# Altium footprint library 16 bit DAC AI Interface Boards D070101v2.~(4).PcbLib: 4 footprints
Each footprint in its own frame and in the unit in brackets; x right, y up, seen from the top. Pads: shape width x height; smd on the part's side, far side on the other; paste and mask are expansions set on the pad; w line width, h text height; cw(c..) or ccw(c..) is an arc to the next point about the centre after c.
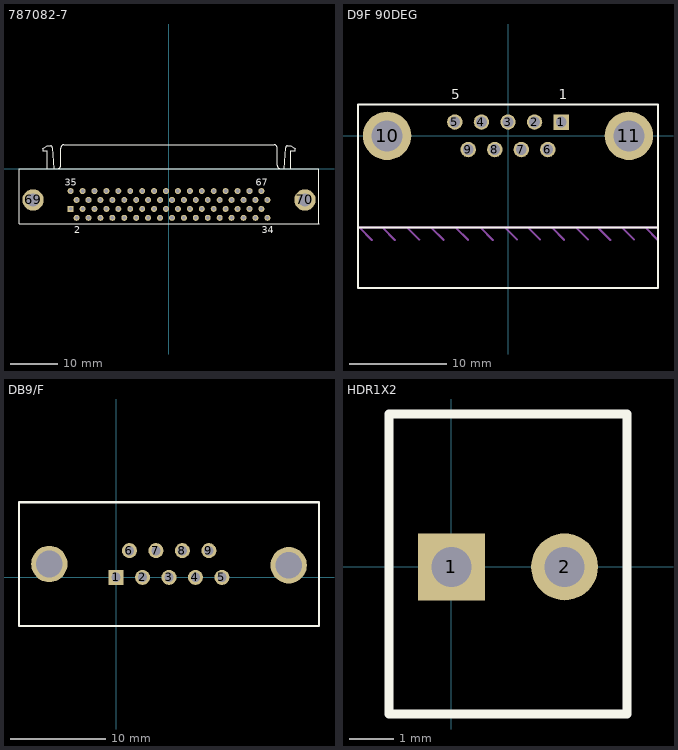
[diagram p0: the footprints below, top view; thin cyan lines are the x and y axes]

## 787082-7 [mm] "Connector; D Subminiature 050 Series; 68 Position; Right Angle"
height 10.44
pads (70):
  rect 1.27x1.27 hole 0.762: 1(-20.955,-8.555)
  round 1.27 hole 0.762: 2(-19.685,-10.46) 3(-18.415,-8.555) 4(-17.145,-10.46) 5(-15.875,-8.555) 6(-14.605,-10.46) 7(-13.335,-8.555) 8(-12.065,-10.46) 9(-10.795,-8.555) 10(-9.525,-10.46) 11(-8.255,-8.555) 12(-6.985,-10.46) 13(-5.715,-8.555) 14(-4.445,-10.46) 15(-3.175,-8.555) 16(-1.905,-10.46) 17(-0.635,-8.555) 18(0.635,-10.46) 19(1.905,-8.555) 20(3.175,-10.46) 21(4.445,-8.555) 22(5.715,-10.46) 23(6.985,-8.555) 24(8.255,-10.46) 25(9.525,-8.555) 26(10.795,-10.46) 27(12.065,-8.555) 28(13.335,-10.46) 29(14.605,-8.555) 30(15.875,-10.46) 31(17.145,-8.555) 32(18.415,-10.46) 33(19.685,-8.555) 34(20.955,-10.46) 35(-20.955,-4.745) 36(-19.685,-6.65) 37(-18.415,-4.745) 38(-17.145,-6.65) 39(-15.875,-4.745) 40(-14.605,-6.65) 41(-13.335,-4.745) 42(-12.065,-6.65) 43(-10.795,-4.745) 44(-9.525,-6.65) 45(-8.255,-4.745) 46(-6.985,-6.65) 47(-5.715,-4.745) 48(-4.445,-6.65) 49(-3.175,-4.745) 50(-1.905,-6.65) 51(-0.635,-4.745) 52(0.635,-6.65) 53(1.905,-4.745) 54(3.175,-6.65) 55(4.445,-4.745) 56(5.715,-6.65) 57(6.985,-4.745) 58(8.255,-6.65) 59(9.525,-4.745) 60(10.795,-6.65) 61(12.065,-4.745) 62(13.335,-6.65) 63(14.605,-4.745) 64(15.875,-6.65) 65(17.145,-4.745) 66(18.415,-6.65) 67(19.685,-4.745) 68(20.955,-6.65)
  round 4.55 hole 2.77: 69(-28.955,-6.65) 70(28.955,-6.65)
Top Overlay:
  lines w0.2: -26.84,4.27 -25.9,4.898 -25.178,4.898 cw(c-25.28,4.5) -24.87,4.5 ; -26.826,4.255 ccw(c-26.6,4.01) -26.85,3.79 -25.97,3.79 -25.97,0 ; -24.87,4.52 -24.5,0 ; -23.76,0.005 ccw(c-23.76,0.7) -23.065,0.7 -23.065,4.4 cw(c-22.37,4.4) -22.37,5.095 ; -22.37,5.11 22.37,5.11 ; 22.37,5.095 cw(c22.37,4.4) 23.065,4.4 23.065,0.7 ccw(c23.76,0.7) 23.76,0.005 ; 24.5,0 24.87,4.52 ; 24.87,4.5 cw(c25.28,4.5) 25.178,4.898 25.9,4.898 26.84,4.27 ; 25.97,0 25.97,3.79 26.85,3.79 ccw(c26.6,4.01) 26.826,4.255 ; -31.95,-11.76 31.95,-11.76 31.95,0 -31.95,0 -31.95,-11.76
  text "2" at -20.185,-13.735 h1.5
  text "34" at 19.705,-13.735 h1.5
  text "67" at 18.435,-3.62 h1.5
  text "35" at -22.205,-3.62 h1.5

## D9F 90DEG [mm]
pads (11):
  rect 1.6x1.6 hole 1.1: 1(5.486,1.422)
  round 1.6 hole 1.1: 2(2.743,1.422) 3(0,1.422) 4(-2.743,1.422) 5(-5.486,1.422) 6(4.115,-1.422) 7(1.372,-1.422) 8(-1.365,-1.422) 9(-4.115,-1.422)
  round 5 hole 3.2: 10(-12.497,0) 11(12.497,0)
Top Overlay:
  lines w0.2: -15.5,-9.5 15.5,-9.5 ; -15.5,-15.75 15.5,-15.75 15.5,3.25 -15.5,3.25 -15.5,-15.75
  text "1" at 5.25,3.75 h1
  text "5" at -5.842,3.75 h1
Mechanical 1:
  lines w0.2: -15.494,-9.5 15.494,-9.5 ; -15.337,-9.5 -14.067,-10.77 ; -12.924,-9.525 -11.679,-10.77 ; -10.409,-9.5 -9.165,-10.745 ; -7.92,-9.5 -6.65,-10.77 ; -5.38,-9.5 -4.11,-10.77 ; -2.84,-9.5 -1.57,-10.77 ; -0.3,-9.5 0.945,-10.745 ; 2.138,-9.551 3.332,-10.745 ; 4.551,-9.525 5.796,-10.77 ; 7.066,-9.5 8.285,-10.719 ; 9.403,-9.602 10.571,-10.77 ; 11.816,-9.525 13.035,-10.745 ; 14.254,-9.525 15.499,-10.77
  text "MTG. SURFACE" at 7.193,-7.697 h1.27
3D body "D9F 90deg.stp": height 12.56, standoff -3.25, extent -15.494,-15.714 15.494,3.181

## DB9/F [mil]
height 68.9
pads (11):
  rect 62x62 hole 38: 1(0,0)
  round 62 hole 38: 2(109,0) 3(218,0) 4(327,0) 5(436,0) 6(55,110) 7(164,110) 8(273,110) 9(382,110)
  round 150 hole 110: ""(-275,55) ""(711,50)
Top Overlay:
  lines w8: -400,-200 836,-200 836,310
  lines w10: -400,-200 -400,310 836,310

## HDR1X2 [mm] "Connector; Header; 2 Position"
height 6
pads (2):
  rect 1.5x1.5 hole 0.9: 1(0,0)
  round 1.5 hole 0.9: 2(2.54,0)
Top Overlay:
  lines w0.2: -1.397,-3.302 3.937,-3.302 3.937,3.429 -1.397,3.429 -1.397,-3.302
3D body "MOLEX 2pin 3.96mm (022232021).stp": height 10.68, standoff -3.54, extent -1.194,-3.099 3.734,3.251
